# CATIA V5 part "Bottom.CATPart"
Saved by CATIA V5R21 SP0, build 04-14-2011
Part number: Fix_Base.1
Bounding box of the stored display mesh (mm): x -90 to 90, y -85 to 85, z 0 to 2.8
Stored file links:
  C:\Users\Pouria\Desktop\Box\Assembled\Bottom.CATPart
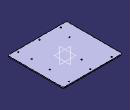
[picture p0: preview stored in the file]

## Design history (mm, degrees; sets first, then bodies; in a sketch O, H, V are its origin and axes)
Body1 (main body)
  Sketch1 on xy-plane, origin (0, 0, 0), H (1, 0, 0), V (0, 1, 0)
    line L1 (80, 70) -> (80, -70)
    line L2 (80, -70) -> (-80, -70)
    line L3 (-80, -70) -> (-80, 70)
    line L4 (-80, 70) -> (80, 70)
    line L5 (90, 85) -> (90, 40)
    line L6 (90, -85) -> (40, -85)
    line L7 (-90, -85) -> (-90, -40)
    line L8 (-90, 85) -> (-40, 85)
    line L9 (90, 40) -> (92.8, 40)
    line L10 (92.8, 40) -> (92.8, -40)
    line L11 (92.8, -40) -> (90, -40)
    point P12 (90, -40)
    point P13 (-90, 40)
    line L12 (-90, 40) -> (-92.8, 40)
    line L13 (-92.8, 40) -> (-92.8, -40)
    line L14 (-92.8, -40) -> (-90, -40)
    point P17 (40, 85)
    line L15 (40, 85) -> (40, 87.8)
    line L16 (40, 87.8) -> (-40, 87.8)
    line L17 (-40, 87.8) -> (-40, 85)
    line L18 (40, -85) -> (40, -87.8)
    line L19 (40, -87.8) -> (-40, -87.8)
    line L20 (-40, -87.8) -> (-40, -85)
    point P24 (-40, -85)
    line L21 (90, -40) -> (90, -85)
    line L22 (40, 85) -> (90, 85)
    line L23 (-90, 40) -> (-90, 85)
    line L24 (-40, -85) -> (-90, -85)
    circle A1 centre (0, 77.5) radius 1.9
    point P25 (0, 77.5)
    circle A2 centre (0, -77.5) radius 1.9
    point P26 (0, -77.5)
    circle A3 centre (65, 77.5) radius 1.9
    point P27 (65, 77.5)
    circle A4 centre (-65, 77.5) radius 1.9
    point P28 (-65, 77.5)
    circle A5 centre (-65, -77.5) radius 1.9
    point P29 (-65, -77.5)
    circle A6 centre (-45, -77.5) radius 1.5
    point P30 (-45, -77.5)
    circle A7 centre (45, -77.5) radius 1.5
    point P31 (45, -77.5)
    circle A8 centre (65, -77.5) radius 1.9
    point P32 (65, -77.5)
    circle A9 centre (45, 77.5) radius 1.5
    point P33 (45, 77.5)
    circle A10 centre (-45, 77.5) radius 1.5
    point P34 (-45, 77.5)
    distance L1 L5 = 10
    distance L2 L6 = 15
    distance L1 L3 = 160
    distance L4 L2 = 140
    length L11 = 2.8
    length L15 = 2.8
    length L10 = 80
    length L16 = 80
    distance P25 L4 = 7.5
    distance P33 L4 = 7.5
    distance P27 L4 = 7.5
    distance P34 L4 = 7.5
    distance P28 L4 = 7.5
    distance P29 L2 = 7.5
    distance P30 L2 = 7.5
    distance P26 L2 = 7.5
    distance P31 L2 = 7.5
    distance P32 L2 = 7.5
    distance P32 L21 = 25
    distance P29 L7 = 25
    distance P27 L5 = 25
    distance P28 L23 = 25
    radius A3 = 1.9
    radius A4 = 1.9
    radius A1 = 1.9
    radius A8 = 1.9
    radius A2 = 1.9
    radius A5 = 1.9
    distance P33 L5 = 45
    distance P34 L23 = 45
    distance P31 L21 = 45
    distance P30 L7 = 45
    radius A7 = 1.5
    radius A6 = 1.5
    radius A9 = 1.5
    radius A10 = 1.5
    vertical: L1 V, L3 V, L5 V, L7 V, L10 V, L13 V, L15 V, L17 V, L18 V, L20 V, L21 V, L23 V
    horizontal: L2 H, L4 H, L6 H, L8 H, L9 H, L11 H, L12 H, L14 H, L16 H, L19 H, L22 H, L24 H
    equidistance: L1 L3 O, L2 L4 O, L5 L7 O, L6 L8 O
    coincidence: P12 L5, P13 L7, P17 L8, P24 L6, L18 L15, L20 L17, L11 L14, L9 L12, L5 L21, L8 L22, L7 L23, L6 L24, P25 V, P26 V
    symmetry: L10 L13 V, L19 L16 H, L15 L17 V, L18 L20 V, L11 L9 H, L14 L12 H
  Pad1: profile Sketch1, direction (0, 0, 1), length 2.8
  Fillet1: radius 10, on edge [face of Pad1 from Sketch1.L4 | face of Pad1 from Sketch1.L3]; edge [face of Pad1 from Sketch1.L1 | face of Pad1 from Sketch1.L4]; edge [face of Pad1 from Sketch1.L2 | face of Pad1 from Sketch1.L1]; edge [face of Pad1 from Sketch1.L3 | face of Pad1 from Sketch1.L2]
  Sketch2 on end face of Pad1, origin (0, 0, 2.8), H (1, 0, 0), V (0, 1, 0)
    line L1 (101.4426, 49.6819) -> (90, 49.6819)
    line L2 (90, 49.6819) -> (90, -51.9452)
    line L3 (90, -51.9452) -> (101.4426, -51.9452)
    line L4 (101.4426, -51.9452) -> (101.4426, 49.6819)
    line L5 (-45.6857, 92.692) -> (55.6289, 92.692)
    line L6 (55.6289, 92.692) -> (55.6289, 85)
    line L7 (55.6289, 85) -> (-45.6857, 85)
    line L8 (-45.6857, 85) -> (-45.6857, 92.692)
    line L9 (-112.17, 48.0503) -> (-90, 48.0503)
    line L10 (-90, 48.0503) -> (-90, -46.351)
    line L11 (-90, -46.351) -> (-112.17, -46.351)
    line L12 (-112.17, -46.351) -> (-112.17, 48.0503)
    line L13 (-47.757, -92.9251) -> (52.604, -92.9251)
    line L14 (52.604, -92.9251) -> (52.604, -85)
    line L15 (52.604, -85) -> (-47.757, -85)
    line L16 (-47.757, -85) -> (-47.757, -92.9251)
    reference projected line E1 (40, -85) -> (90, -85) from edge [face of Pad1 from Sketch1.L6 | end face of Pad1]
    reference projected line E2 (90, -85) -> (90, -40) from edge [face of Pad1 from Sketch1.L21 | end face of Pad1]
    reference projected line E3 (90, 85) -> (40, 85) from edge [face of Pad1 from Sketch1.L22 | end face of Pad1]
    reference projected line E4 (-90, -40) -> (-90, -85) from edge [face of Pad1 from Sketch1.L7 | end face of Pad1]
    horizontal: L1 H, L3 H, L5 H, L7 H, L9 H, L11 H, L13 H, L15 H
    vertical: L2 V, L4 V, L6 V, L8 V, L10 V, L12 V, L14 V, L16 V
    coincidence: L15 E1, L2 E2, L7 E3, L10 E4
  Pocket1: profile Sketch2, direction (0, 0, -1), up to start face of Pad1
  Sketch3 on end face of Pad1, origin (0, 0, 2.8), H (1, 0, 0), V (0, 1, 0)
    circle A1 centre (-12.5, 38.75) radius 1.75
    point P1 (-12.5, 38.75)
    circle A2 centre (62.5, 16.25) radius 1.75
    point P2 (62.5, 16.25)
    circle A3 centre (62.5, -38.75) radius 1.75
    point P3 (62.5, -38.75)
    circle A4 centre (-52.5, -38.75) radius 1.75
    point P4 (-52.5, -38.75)
    line L1 (88, 83) -> (88, -83)
    line L2 (88, -83) -> (-88, -83)
    line L3 (-88, -83) -> (-88, 83)
    line L4 (-88, 83) -> (88, 83)
    reference projected line E1 (40, 85) -> (90, 85) from edge [face of Pad1 | end face of Pad1]
    reference projected line E3 (90, 85) -> (90, 40) from edge [face of Pad1 | end face of Pad1]
    circle A5 centre (65, -77.5) radius 2.5
    circle A6 centre (0, -77.5) radius 2.5
    circle A7 centre (-65, -77.5) radius 2.5
    circle A8 centre (-65, 77.5) radius 2.5
    circle A9 centre (0, 77.5) radius 2.5
    circle A10 centre (65, 77.5) radius 2.5
    reference projected circle E5 centre (65, 77.5) radius 1.9 from edge [end face of Pad1 | face of Pad1 from Sketch1.A3]
    reference projected circle E6 centre (0, 77.5) radius 1.9 from edge [end face of Pad1 | face of Pad1 from Sketch1.A1]
    reference projected circle E7 centre (-65, 77.5) radius 1.9 from edge [end face of Pad1 | face of Pad1 from Sketch1.A4]
    reference projected circle E8 centre (65, -77.5) radius 1.9 from edge [end face of Pad1 | face of Pad1 from Sketch1.A8]
    reference projected circle E9 centre (0, -77.5) radius 1.9 from edge [end face of Pad1 | face of Pad1 from Sketch1.A2]
    reference projected circle E10 centre (-65, -77.5) radius 1.9 from edge [end face of Pad1 | face of Pad1 from Sketch1.A5]
    radius A1 = 1.75
    radius A2 = 1.75
    radius A3 = 1.75
    radius A4 = 1.75
    distance P2 V = 62.5
    distance P2 H = 16.25
    distance P1 V = 12.5
    distance P1 H = 38.75
    distance P4 V = 52.5
    distance P4 H = 38.75
    distance P3 V = 62.5
    distance P3 H = 38.75
    distance L4 E1 = 2
    distance L1 E3 = 2
    radius A5 = 2.5
    radius A6 = 2.5
    radius A7 = 2.5
    radius A10 = 2.5
    radius A9 = 2.5
    radius A8 = 2.5
    vertical: L1 V, L3 V
    horizontal: L2 H, L4 H
    equidistance: L1 L3 O, L2 L4 O
    concentricity: A10 E5, A9 E6, A8 E7, A5 E8, A6 E9, A7 E10
  Pad2: profile Sketch3, direction (0, 0, 1), up to start face of Pad1
  Fillet2: radius 5, on edge [face of Pad1 | face of Pad1] (x4)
